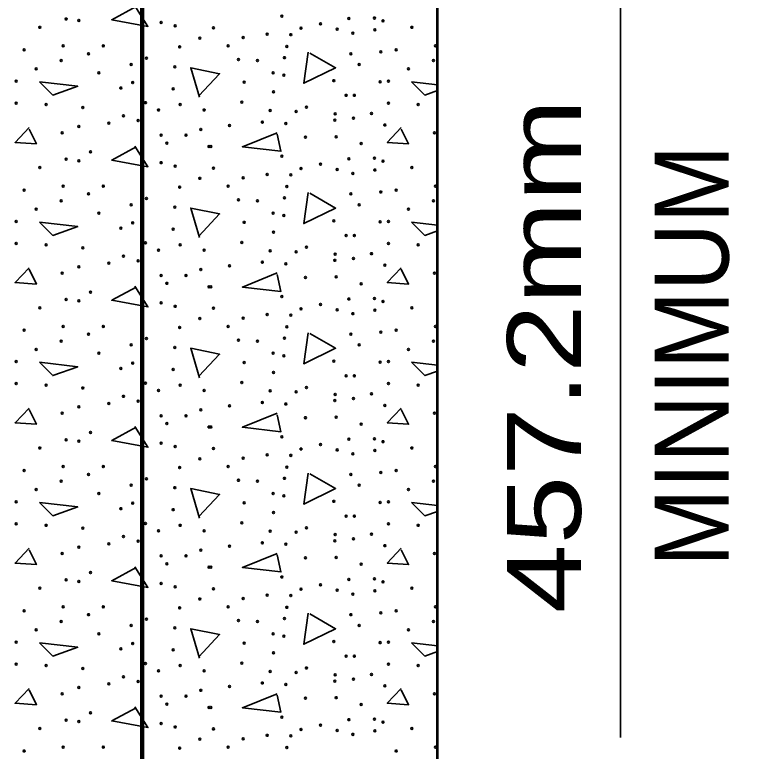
# Model space of a CAD drawing. Extents: x 442 to 1297, y -1132 to -588.
# Drawn here: x 575.62 to 600.05, y -937.82 to -913.86 of the extents above; entities that cross this region are included whole.
import ezdxf
from ezdxf.enums import TextEntityAlignment as Align

# ---------------------------------------------------------------- set-up
doc = ezdxf.new("R2010")
doc.units = 0
doc.header["$LTSCALE"] = 0.96
doc.layers.add('1', color=7, linetype='Continuous', lineweight=35)

msp = doc.modelspace()

# ---------------------------------------------------------------- linework, layer by layer
at = {"layer": '1', "lineweight": 106}
msp.add_line((579.7476, -971.1675), (579.7476, -893.8481), dxfattribs=at)
at = {"layer": '1'}
for p, q in [((595.2907, -895.6076), (595.2907, -937.3524)), ((588.5054, -916.0307), (589.3476, -916.1279)), ((588.5054, -920.5907), (589.3476, -920.6879)), ((588.5054, -925.1507), (589.3476, -925.2479)), ((588.5054, -929.7107), (589.3476, -929.8079)), ((588.5054, -934.2707), (589.3476, -934.3679))]:
    msp.add_line(p, q, dxfattribs=at)
at = {"layer": '1', "lineweight": 53}
msp.add_lwpolyline([(621.7985, -981.2615), (621.7985, -962.7675), (589.3476, -961.5675), (589.3476, -902.8076), (585.7476, -902.8076), (585.7476, -889.0076), (577.3476, -889.0076), (577.3476, -884.2076)], dxfattribs=at)
at = {"layer": '1'}
for points in [[(579.5534, -913.5827), (578.7614, -914.0147), (579.9374, -914.2307), (579.5054, -913.5587)], [(585.1934, -915.0947), (586.0334, -915.5747), (585.0014, -916.0787), (585.1454, -915.0707)], [(581.6174, -916.5347), (581.3294, -915.5747), (582.2654, -915.7667), (581.5934, -916.4867)], [(589.3476, -916.3179), (588.9374, -916.4627), (588.5054, -916.0307)], [(576.0734, -917.5187), (575.6174, -917.9987), (576.3134, -918.0467), (576.0734, -917.5667)], [(588.1694, -917.5187), (587.7134, -917.9987), (588.4094, -918.0467), (588.1694, -917.5667)], [(584.1374, -917.6867), (583.0094, -918.1427), (584.2574, -918.2867), (584.1374, -917.7347)], [(579.5534, -918.1427), (578.7614, -918.5747), (579.9374, -918.7907), (579.5054, -918.1187)], [(585.1934, -919.6547), (586.0334, -920.1347), (585.0014, -920.6387), (585.1454, -919.6307)], [(581.6174, -921.0947), (581.3294, -920.1347), (582.2654, -920.3267), (581.5934, -921.0467)], [(589.3476, -920.8779), (588.9374, -921.0227), (588.5054, -920.5907)], [(576.0734, -922.0787), (575.6174, -922.5587), (576.3134, -922.6067), (576.0734, -922.1267)], [(584.1374, -922.2467), (583.0094, -922.7027), (584.2574, -922.8467), (584.1374, -922.2947)], [(588.1694, -922.0787), (587.7134, -922.5587), (588.4094, -922.6067), (588.1694, -922.1267)], [(579.5534, -922.7027), (578.7614, -923.1347), (579.9374, -923.3507), (579.5054, -922.6787)], [(585.1934, -924.2147), (586.0334, -924.6947), (585.0014, -925.1987), (585.1454, -924.1907)], [(581.6174, -925.6547), (581.3294, -924.6947), (582.2654, -924.8867), (581.5934, -925.6067)], [(589.3476, -925.4379), (588.9374, -925.5827), (588.5054, -925.1507)], [(576.0734, -926.6387), (575.6174, -927.1187), (576.3134, -927.1667), (576.0734, -926.6867)], [(588.1694, -926.6387), (587.7134, -927.1187), (588.4094, -927.1667), (588.1694, -926.6867)], [(584.1374, -926.8067), (583.0094, -927.2627), (584.2574, -927.4067), (584.1374, -926.8547)], [(579.5534, -927.2627), (578.7614, -927.6947), (579.9374, -927.9107), (579.5054, -927.2387)], [(585.1934, -928.7747), (586.0334, -929.2547), (585.0014, -929.7587), (585.1454, -928.7507)], [(581.6174, -930.2147), (581.3294, -929.2547), (582.2654, -929.4467), (581.5934, -930.1667)], [(589.3476, -929.9979), (588.9374, -930.1427), (588.5054, -929.7107)], [(576.0734, -931.1987), (575.6174, -931.6787), (576.3134, -931.7267), (576.0734, -931.2467)], [(588.1694, -931.1987), (587.7134, -931.6787), (588.4094, -931.7267), (588.1694, -931.2467)], [(584.1374, -931.3667), (583.0094, -931.8227), (584.2574, -931.9667), (584.1374, -931.4147)], [(579.5534, -931.8227), (578.7614, -932.2547), (579.9374, -932.4707), (579.5054, -931.7987)], [(585.1934, -933.3347), (586.0334, -933.8147), (585.0014, -934.3187), (585.1454, -933.3107)], [(581.6174, -934.7747), (581.3294, -933.8147), (582.2654, -934.0067), (581.5934, -934.7267)], [(589.3476, -934.5579), (588.9374, -934.7027), (588.5054, -934.2707)], [(576.0734, -935.7587), (575.6174, -936.2387), (576.3134, -936.2867), (576.0734, -935.8067)], [(584.1374, -935.9267), (583.0094, -936.3827), (584.2574, -936.5267), (584.1374, -935.9747)], [(588.1694, -935.7587), (587.7134, -936.2387), (588.4094, -936.2867), (588.1694, -935.8067)], [(579.5534, -936.3827), (578.7614, -936.8147), (579.9374, -937.0307), (579.5054, -936.3587)]]:
    msp.add_lwpolyline(points, dxfattribs=at)
for points in [[(576.4094, -916.0307), (577.6574, -916.1747), (576.8414, -916.4627)], [(576.4094, -920.5907), (577.6574, -920.7347), (576.8414, -921.0227)], [(576.4094, -925.1507), (577.6574, -925.2947), (576.8414, -925.5827)], [(576.4094, -929.7107), (577.6574, -929.8547), (576.8414, -930.1427)], [(576.4094, -934.2707), (577.6574, -934.4147), (576.8414, -934.7027)]]:
    msp.add_lwpolyline(points, close=True, dxfattribs=at)
for centre in [(584.2911, -913.8923), (586.4699, -913.9718), (587.297, -913.9559), (577.2776, -913.9878), (577.6912, -914.0355), (580.363, -914.0992), (580.8241, -914.2104), (585.5475, -914.1468), (587.5765, -914.0514), (576.4188, -914.2582), (582.0647, -914.2741), (584.9114, -914.2901), (586.0883, -914.3218), (586.5973, -914.4491), (587.3128, -914.3377), (588.5148, -914.2582), (581.6193, -914.6082), (583.0348, -914.5923), (583.8141, -914.4809), (584.5774, -914.4968), (577.1821, -914.8627), (578.4863, -914.8627), (580.9673, -914.8946), (582.5418, -914.8627), (584.4502, -914.8786), (589.2781, -914.8627), (575.9098, -914.99), (578.0092, -915.1172), (586.5335, -915.1172), (587.5037, -915.0536), (588.0058, -914.99), (577.1186, -915.34), (579.8858, -915.2605), (582.8757, -915.3082), (583.4959, -915.34), (584.3707, -915.2445), (589.2146, -915.34), (576.3075, -915.6105), (579.3928, -915.4673), (580.8082, -915.5468), (586.804, -915.4673), (588.4035, -915.6105), (578.3431, -915.7378), (584.0049, -915.7378), (584.3548, -915.8173), (575.6554, -916.0081), (579.4406, -916.0559), (583.0665, -916.04), (585.9769, -915.9923), (587.4801, -916.0268), (587.7514, -916.0081), (579.0588, -916.2309), (580.7605, -916.2627), (584.0208, -916.3582), (586.3746, -916.4696), (586.6449, -916.4696), (575.6554, -916.7241), (576.6256, -916.7718), (577.8184, -916.8672), (579.854, -916.7082), (580.9832, -916.7718), (582.9871, -916.6922), (585.0864, -916.8514), (587.7514, -916.7241), (588.7216, -916.7718), (579.1384, -917.1377), (580.2834, -916.9469), (581.7625, -916.9469), (583.9095, -916.9627), (584.7524, -916.9945), (586.0247, -917.0741), (587.2015, -917.0581), (578.6613, -917.3705), (579.6154, -917.291), (583.655, -917.3387), (584.4184, -917.3865), (586.0088, -917.2751), (586.6131, -917.2115), (577.6912, -917.4819), (581.6512, -917.5773), (582.5894, -917.4501), (587.6401, -917.4341), (577.1504, -917.6887), (580.3629, -917.7682), (581.174, -917.7682), (585.0545, -917.8319), (586.0565, -917.816), (589.2464, -917.6887), (580.5538, -918.0228), (581.9215, -918.1341), (581.9851, -918.1341), (586.8676, -918.0386), (578.0728, -918.3091), (577.2776, -918.5478), (577.6912, -918.5955), (584.2911, -918.4523), (586.4699, -918.5318), (587.297, -918.5159), (587.5765, -918.6114), (576.4188, -918.8182), (580.363, -918.6592), (580.8241, -918.7704), (582.0647, -918.8341), (584.9114, -918.8501), (585.5475, -918.7068), (588.5148, -918.8182), (583.8141, -919.0409), (584.5774, -919.0568), (586.0883, -918.8818), (586.5973, -919.0091), (587.3128, -918.8977), (581.6193, -919.1682), (583.0348, -919.1523), (575.9098, -919.55), (577.1821, -919.4227), (578.4863, -919.4227), (580.9673, -919.4546), (582.5418, -919.4227), (584.4502, -919.4386), (588.0058, -919.55), (589.2781, -919.4227), (578.0092, -919.6772), (579.8858, -919.8205), (584.3707, -919.8045), (586.5335, -919.6772), (587.5037, -919.6136), (577.1186, -919.9), (579.3928, -920.0273), (582.8757, -919.8682), (583.4959, -919.9), (586.804, -920.0273), (589.2146, -919.9), (576.3075, -920.1705), (578.3431, -920.2978), (580.8082, -920.1068), (584.0049, -920.2978), (588.4035, -920.1705), (575.6554, -920.5681), (584.3548, -920.3773), (585.9769, -920.5523), (587.7514, -920.5681), (579.0588, -920.7909), (579.4406, -920.6159), (580.7605, -920.8227), (583.0665, -920.6), (587.4801, -920.5868), (584.0208, -920.9182), (586.3746, -921.0296), (586.6449, -921.0296), (575.6554, -921.2841), (579.854, -921.2682), (582.9871, -921.2522), (587.7514, -921.2841), (576.6256, -921.3318), (577.8184, -921.4272), (580.2834, -921.5069), (580.9832, -921.3318), (581.7625, -921.5069), (583.9095, -921.5227), (584.7524, -921.5545), (585.0864, -921.4114), (588.7216, -921.3318), (579.1384, -921.6977), (586.0247, -921.6341), (586.6131, -921.7715), (587.2015, -921.6181), (577.6912, -922.0419), (578.6613, -921.9305), (579.6154, -921.851), (582.5894, -922.0101), (583.655, -921.8987), (584.4184, -921.9465), (586.0088, -921.8351), (587.6401, -921.9941), (577.1504, -922.2487), (581.6512, -922.1373), (589.2464, -922.2487), (580.3629, -922.3282), (581.174, -922.3282), (585.0545, -922.3919), (586.0565, -922.376), (580.5538, -922.5828), (581.9215, -922.6941), (581.9851, -922.6941), (586.8676, -922.5986), (578.0728, -922.8691), (584.2911, -923.0123), (577.2776, -923.1078), (577.6912, -923.1555), (580.363, -923.2192), (585.5475, -923.2668), (586.4699, -923.0918), (587.297, -923.0759), (587.5765, -923.1714), (576.4188, -923.3782), (580.8241, -923.3304), (582.0647, -923.3941), (584.9114, -923.4101), (586.0883, -923.4418), (587.3128, -923.4577), (588.5148, -923.3782), (581.6193, -923.7282), (583.0348, -923.7123), (583.8141, -923.6009), (584.5774, -923.6168), (586.5973, -923.5691), (577.1821, -923.9827), (578.4863, -923.9827), (582.5418, -923.9827), (584.4502, -923.9986), (589.2781, -923.9827), (575.9098, -924.11), (578.0092, -924.2372), (580.9673, -924.0146), (586.5335, -924.2372), (587.5037, -924.1736), (588.0058, -924.11), (577.1186, -924.46), (579.8858, -924.3805), (582.8757, -924.4282), (583.4959, -924.46), (584.3707, -924.3645), (589.2146, -924.46), (576.3075, -924.7305), (579.3928, -924.5873), (580.8082, -924.6668), (586.804, -924.5873), (588.4035, -924.7305), (578.3431, -924.8578), (584.0049, -924.8578), (584.3548, -924.9373), (575.6554, -925.1281), (579.4406, -925.1759), (583.0665, -925.16), (585.9769, -925.1123), (587.4801, -925.1468), (587.7514, -925.1281), (579.0588, -925.3509), (580.7605, -925.3827), (584.0208, -925.4782), (586.3746, -925.5896), (586.6449, -925.5896), (575.6554, -925.8441), (576.6256, -925.8918), (579.854, -925.8282), (580.9832, -925.8918), (582.9871, -925.8122), (587.7514, -925.8441), (588.7216, -925.8918), (577.8184, -925.9872), (580.2834, -926.0669), (581.7625, -926.0669), (583.9095, -926.0827), (584.7524, -926.1145), (585.0864, -925.9714), (586.0247, -926.1941), (587.2015, -926.1781), (579.1384, -926.2577), (579.6154, -926.411), (586.0088, -926.3951), (586.6131, -926.3315), (577.6912, -926.6019), (578.6613, -926.4905), (582.5894, -926.5701), (583.655, -926.4587), (584.4184, -926.5065), (587.6401, -926.5541), (577.1504, -926.8087), (580.3629, -926.8882), (581.174, -926.8882), (581.6512, -926.6973), (586.0565, -926.936), (589.2464, -926.8087), (580.5538, -927.1428), (585.0545, -926.9519), (586.8676, -927.1586), (581.9215, -927.2541), (581.9851, -927.2541), (577.2776, -927.6678), (578.0728, -927.4291), (584.2911, -927.5723), (586.4699, -927.6518), (587.297, -927.6359), (577.6912, -927.7155), (580.363, -927.7792), (580.8241, -927.8904), (585.5475, -927.8268), (587.5765, -927.7314), (576.4188, -927.9382), (582.0647, -927.9541), (584.9114, -927.9701), (586.0883, -928.0018), (586.5973, -928.1291), (587.3128, -928.0177), (588.5148, -927.9382), (581.6193, -928.2882), (583.0348, -928.2723), (583.8141, -928.1609), (584.5774, -928.1768), (577.1821, -928.5427), (578.4863, -928.5427), (580.9673, -928.5746), (582.5418, -928.5427), (584.4502, -928.5586), (589.2781, -928.5427), (575.9098, -928.67), (578.0092, -928.7972), (586.5335, -928.7972), (587.5037, -928.7336), (588.0058, -928.67), (577.1186, -929.02), (579.8858, -928.9405), (582.8757, -928.9882), (583.4959, -929.02), (584.3707, -928.9245), (589.2146, -929.02), (576.3075, -929.2905), (579.3928, -929.1473), (580.8082, -929.2268), (586.804, -929.1473), (588.4035, -929.2905), (578.3431, -929.4178), (584.0049, -929.4178), (584.3548, -929.4973), (575.6554, -929.6881), (579.4406, -929.7359), (583.0665, -929.72), (585.9769, -929.6723), (587.4801, -929.7068), (587.7514, -929.6881), (579.0588, -929.9109), (580.7605, -929.9427), (584.0208, -930.0382), (586.3746, -930.1496), (586.6449, -930.1496), (575.6554, -930.4041), (576.6256, -930.4518), (577.8184, -930.5472), (579.854, -930.3882), (580.9832, -930.4518), (582.9871, -930.3722), (585.0864, -930.5314), (587.7514, -930.4041), (588.7216, -930.4518), (579.1384, -930.8177), (580.2834, -930.6269), (581.7625, -930.6269), (583.9095, -930.6427), (584.7524, -930.6745), (586.0247, -930.7541), (587.2015, -930.7381), (578.6613, -931.0505), (579.6154, -930.971), (583.655, -931.0187), (584.4184, -931.0665), (586.0088, -930.9551), (586.6131, -930.8915), (577.6912, -931.1619), (581.6512, -931.2573), (582.5894, -931.1301), (587.6401, -931.1141), (577.1504, -931.3687), (580.3629, -931.4482), (581.174, -931.4482), (585.0545, -931.5119), (586.0565, -931.496), (589.2464, -931.3687), (580.5538, -931.7028), (581.9215, -931.8141), (581.9851, -931.8141), (586.8676, -931.7186), (578.0728, -931.9891), (577.2776, -932.2278), (577.6912, -932.2755), (584.2911, -932.1323), (586.4699, -932.2118), (587.297, -932.1959), (587.5765, -932.2914), (576.4188, -932.4982), (580.363, -932.3392), (580.8241, -932.4504), (582.0647, -932.5141), (584.9114, -932.5301), (585.5475, -932.3868), (588.5148, -932.4982), (583.8141, -932.7209), (584.5774, -932.7368), (586.0883, -932.5618), (586.5973, -932.6891), (587.3128, -932.5777), (581.6193, -932.8482), (583.0348, -932.8323), (575.9098, -933.23), (577.1821, -933.1027), (578.4863, -933.1027), (580.9673, -933.1346), (582.5418, -933.1027), (584.4502, -933.1186), (588.0058, -933.23), (589.2781, -933.1027), (578.0092, -933.3572), (579.8858, -933.5005), (584.3707, -933.4845), (586.5335, -933.3572), (587.5037, -933.2936), (577.1186, -933.58), (579.3928, -933.7073), (582.8757, -933.5482), (583.4959, -933.58), (586.804, -933.7073), (589.2146, -933.58), (576.3075, -933.8505), (578.3431, -933.9778), (580.8082, -933.7868), (584.0049, -933.9778), (588.4035, -933.8505), (575.6554, -934.2481), (584.3548, -934.0573), (585.9769, -934.2323), (587.4801, -934.2668), (587.7514, -934.2481), (579.0588, -934.4709), (579.4406, -934.2959), (580.7605, -934.5027), (583.0665, -934.28), (584.0208, -934.5982), (586.3746, -934.7096), (586.6449, -934.7096), (575.6554, -934.9641), (579.854, -934.9482), (582.9871, -934.9322), (587.7514, -934.9641), (576.6256, -935.0118), (577.8184, -935.1072), (580.2834, -935.1869), (580.9832, -935.0118), (581.7625, -935.1869), (583.9095, -935.2027), (584.7524, -935.2345), (585.0864, -935.0914), (588.7216, -935.0118), (579.1384, -935.3777), (586.0247, -935.3141), (586.6131, -935.4515), (587.2015, -935.2981), (577.6912, -935.7219), (578.6613, -935.6105), (579.6154, -935.531), (582.5894, -935.6901), (583.655, -935.5787), (584.4184, -935.6265), (586.0088, -935.5151), (587.6401, -935.6741), (577.1504, -935.9287), (581.6512, -935.8173), (589.2464, -935.9287), (580.3629, -936.0082), (581.174, -936.0082), (585.0545, -936.0719), (586.0565, -936.056), (580.5538, -936.2628), (581.9215, -936.3741), (581.9851, -936.3741), (586.8676, -936.2786), (578.0728, -936.5491), (584.2911, -936.6923), (577.2776, -936.7878), (577.6912, -936.8355), (580.363, -936.8992), (585.5475, -936.9468), (586.4699, -936.7718), (587.297, -936.7559), (587.5765, -936.8514), (576.4188, -937.0582), (580.8241, -937.0104), (582.0647, -937.0741), (584.9114, -937.0901), (586.0883, -937.1218), (587.3128, -937.1377), (588.5148, -937.0582), (581.6193, -937.4082), (583.0348, -937.3923), (583.8141, -937.2809), (584.5774, -937.2968), (586.5973, -937.2491), (577.1821, -937.6627), (578.4863, -937.6627), (582.5418, -937.6627), (584.4502, -937.6786), (589.2781, -937.6627), (575.9098, -937.79), (580.9673, -937.6946), (588.0058, -937.79)]:
    msp.add_circle(centre, 0.0318, dxfattribs=at)
for centre in [(589.3736, -913.9878), (589.3736, -918.5478), (589.3736, -923.1078), (589.3736, -927.6678), (589.3736, -932.2278), (589.3736, -936.7878)]:
    msp.add_arc(centre, 0.0318, 144.92389, 215.07611, dxfattribs=at)

# ---------------------------------------------------------------- texts
for s, width, p in [('457.2mm', 1.25, (594.008, -924.9438)), ('MINIMUM', 0.95, (598.808, -924.9438))]:
    msp.add_text(s, height=2.4, rotation=90, dxfattribs=dict(at, width=width)).set_placement(p, align=Align.CENTER)

doc.saveas('drawing.dxf')
